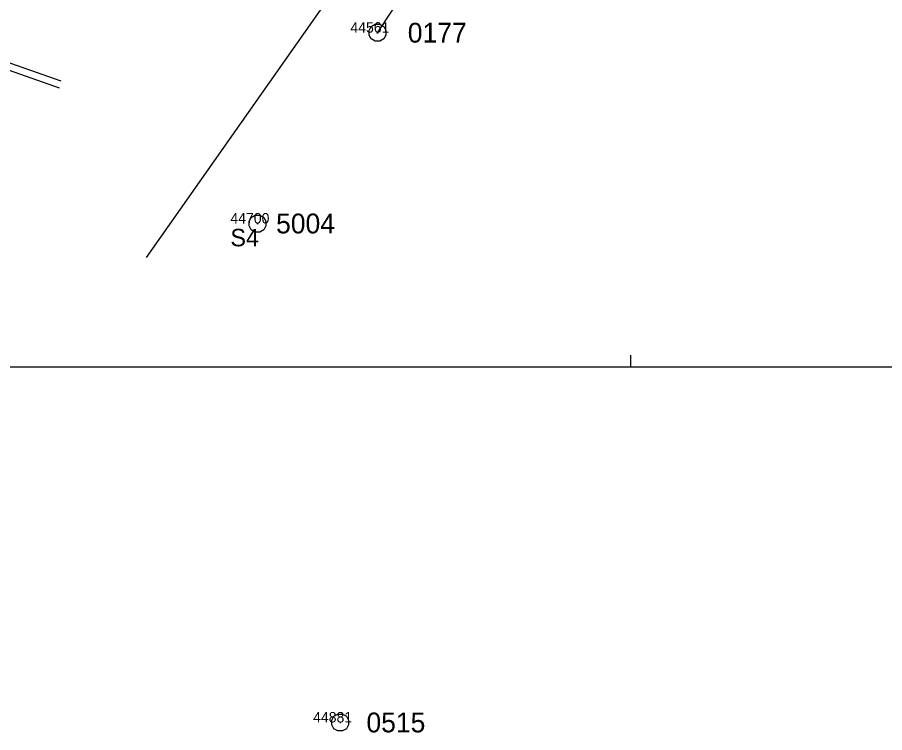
# Model space of a CAD drawing. Extents: x -598521 to -597689, y -1074676 to -1074150.
# Drawn here: x -598447.59 to -598410.36, y -1074239.88 to -1074209.17 of the extents above; entities that cross this region are included whole.
import ezdxf

# ---------------------------------------------------------------- set-up
doc = ezdxf.new("R2010")
doc.units = 0
for name, color, linetype in [('Vrstva 1', 7, 'Continuous'), ('Vrstva 10', 7, 'Continuous'), ('Vrstva 12', 7, 'Continuous'), ('Vrstva 2', 7, 'Continuous'), ('Vrstva 3', 7, 'Continuous'), ('Vrstva 40', 7, 'Continuous')]:
    doc.layers.add(name, color=color, linetype=linetype)

msp = doc.modelspace()

# ---------------------------------------------------------------- linework, layer by layer
at = {"layer": 'Vrstva 1'}
for p, q in [((-598432.155, -1074209.829), (-598432.105, -1074209.829)), ((-598437.305, -1074218.02), (-598437.255, -1074218.02)), ((-598433.755, -1074239.44), (-598433.705, -1074239.44))]:
    msp.add_line(p, q, dxfattribs=at)
for points in [[(-598432.035, -1074209.469), (-598431.865, -1074209.564), (-598431.77, -1074209.734), (-598431.77, -1074209.929), (-598431.865, -1074210.099), (-598432.035, -1074210.194), (-598432.23, -1074210.194), (-598432.4, -1074210.099), (-598432.495, -1074209.929), (-598432.495, -1074209.734), (-598432.4, -1074209.564), (-598432.23, -1074209.469)], [(-598437.185, -1074217.66), (-598437.015, -1074217.755), (-598436.92, -1074217.925), (-598436.92, -1074218.12), (-598437.015, -1074218.29), (-598437.185, -1074218.385), (-598437.38, -1074218.385), (-598437.55, -1074218.29), (-598437.645, -1074218.12), (-598437.645, -1074217.925), (-598437.55, -1074217.755), (-598437.38, -1074217.66)], [(-598433.635, -1074239.08), (-598433.465, -1074239.175), (-598433.37, -1074239.345), (-598433.37, -1074239.54), (-598433.465, -1074239.71), (-598433.635, -1074239.805), (-598433.83, -1074239.805), (-598434, -1074239.71), (-598434.095, -1074239.54), (-598434.095, -1074239.345), (-598434, -1074239.175), (-598433.83, -1074239.08)]]:
    msp.add_lwpolyline(points, close=True, dxfattribs=at)
at = {"layer": 'Vrstva 10'}
for points in [[(-598442.048, -1074219.486), (-598434.374, -1074208.569), (-598430.967, -1074201.161), (-598425.53, -1074195.272), (-598419.866, -1074189.628), (-598414.116, -1074180.898), (-598419.205, -1074177.506), (-598424.611, -1074174.962), (-598434.413, -1074170.349), (-598445.99, -1074163.97), (-598455.971, -1074163.301), (-598463.49, -1074164.656), (-598467.1, -1074166.52), (-598471.036, -1074168.831), (-598472.45, -1074170.18), (-598472.574, -1074170.302), (-598472.62, -1074170.36), (-598472.93, -1074170.67), (-598473.26, -1074171.05)], [(-598432.13, -1074209.829), (-598427.797, -1074203.264), (-598422.092, -1074196.595), (-598417.639, -1074191.389), (-598408.723, -1074183.247), (-598407.365, -1074182.61), (-598405.473, -1074182.867), (-598403.091, -1074183.852), (-598396.104, -1074187.449)], [(-598480.846, -1074217.048), (-598466.668, -1074210.51), (-598452.741, -1074209.434), (-598445.724, -1074211.895)], [(-598480.72, -1074217.32), (-598466.591, -1074210.805), (-598452.781, -1074209.738), (-598445.79, -1074212.19)]]:
    msp.add_lwpolyline(points, dxfattribs=at)
at = {"layer": 'Vrstva 12'}
for points in [[(-598477.856, -1074175.904), (-598479.108, -1074177.873), (-598481.873, -1074181.144), (-598482.714, -1074182.62), (-598484.125, -1074188.19), (-598485.335, -1074196.141), (-598485.114, -1074200.364), (-598484.5, -1074206.655), (-598482.536, -1074211.254), (-598480.207, -1074214.488), (-598467.793, -1074210.214), (-598459.725, -1074208.727), (-598453.744, -1074207.761), (-598434.045, -1074202.26), (-598426.944, -1074195.607), (-598420.2, -1074189.398), (-598414.755, -1074180.164), (-598419.159, -1074177.729), (-598424.716, -1074175.666), (-598432.261, -1074171.95), (-598446.273, -1074165.334), (-598449.284, -1074163.066), (-598455.078, -1074161.455), (-598458.605, -1074161.801), (-598464.281, -1074162.718), (-598468.112, -1074164.562), (-598472.279, -1074167.706), (-598475.138, -1074168.205), (-598476.252, -1074168.916), (-598476.978, -1074169.714), (-598477.609, -1074175.205), (-598477.856, -1074175.904)], [(-598473.789, -1074172.039), (-598475.746, -1074175.895), (-598480.673, -1074186.045), (-598482.671, -1074189.544), (-598484.328, -1074196.236), (-598484.11, -1074202.306), (-598483.768, -1074206.314), (-598481.225, -1074209.94), (-598467.357, -1074209.735), (-598459.946, -1074208.147), (-598451.72, -1074206.172), (-598433.884, -1074198.944), (-598427.582, -1074193.806), (-598421.589, -1074188.753), (-598417.664, -1074181.613), (-598423.377, -1074177.475), (-598435.653, -1074170.84), (-598446.227, -1074166.125), (-598452.854, -1074164.125), (-598463.523, -1074165.086), (-598467.1, -1074166.52), (-598468.291, -1074167.262), (-598470.683, -1074168.7), (-598473.219, -1074171.071)], [(-598473.789, -1074172.039), (-598475.746, -1074175.895), (-598480.673, -1074186.045), (-598482.671, -1074189.544), (-598484.328, -1074196.236), (-598484.11, -1074202.306), (-598483.768, -1074206.314), (-598481.225, -1074209.94), (-598467.357, -1074209.735), (-598459.946, -1074208.147), (-598451.72, -1074206.172), (-598433.884, -1074198.944), (-598427.582, -1074193.806), (-598421.589, -1074188.753), (-598417.664, -1074181.613), (-598423.377, -1074177.475), (-598435.653, -1074170.84), (-598446.227, -1074166.125), (-598452.854, -1074164.125), (-598463.523, -1074165.086), (-598467.1, -1074166.52), (-598468.291, -1074167.262), (-598470.683, -1074168.7), (-598473.219, -1074171.071)], [(-598473.448, -1074172.233), (-598475.58, -1074175.922), (-598480.465, -1074186.125), (-598482.4, -1074189.73), (-598483.981, -1074196.229), (-598483.886, -1074202.253), (-598483.546, -1074205.944), (-598480.979, -1074209.161), (-598475.137, -1074210.074), (-598467.043, -1074208.93), (-598460.057, -1074207.659), (-598451.873, -1074205.694), (-598431.777, -1074196.461), (-598429.106, -1074194.199), (-598419.867, -1074184.797), (-598419.874, -1074181.816), (-598423.69, -1074178.164), (-598435.572, -1074171.16), (-598446.402, -1074166.594), (-598452.796, -1074164.414), (-598463.35, -1074165.396), (-598466.975, -1074166.935), (-598468.113, -1074167.583), (-598470.593, -1074168.979), (-598472.889, -1074171.361)]]:
    msp.add_spline(points, degree=3, dxfattribs=at)
at = {"layer": 'Vrstva 40'}
for p, q in [((-598421.273, -1074223.67), (-598421.273, -1074224.17)), ((-598520.773, -1074224.17), (-598374.273, -1074224.17))]:
    msp.add_line(p, q, dxfattribs=at)

# ---------------------------------------------------------------- texts
at = {"layer": 'Vrstva 10'}
msp.add_text('S4', height=0.75, dxfattribs=at).set_placement((-598438.445, -1074218.999))
at = {"layer": 'Vrstva 2'}
for s, p in [('0177', (-598430.832, -1074210.254)), ('5004', (-598436.484, -1074218.445)), ('0515', (-598432.606, -1074239.865))]:
    msp.add_text(s, height=0.85, dxfattribs=at).set_placement(p)
at = {"layer": 'Vrstva 3'}
for s, p in [('44561', (-598433.294, -1074209.829)), ('44700', (-598438.444, -1074218.02)), ('44881', (-598434.894, -1074239.44))]:
    msp.add_text(s, height=0.45, dxfattribs=at).set_placement(p)

doc.saveas('drawing.dxf')
